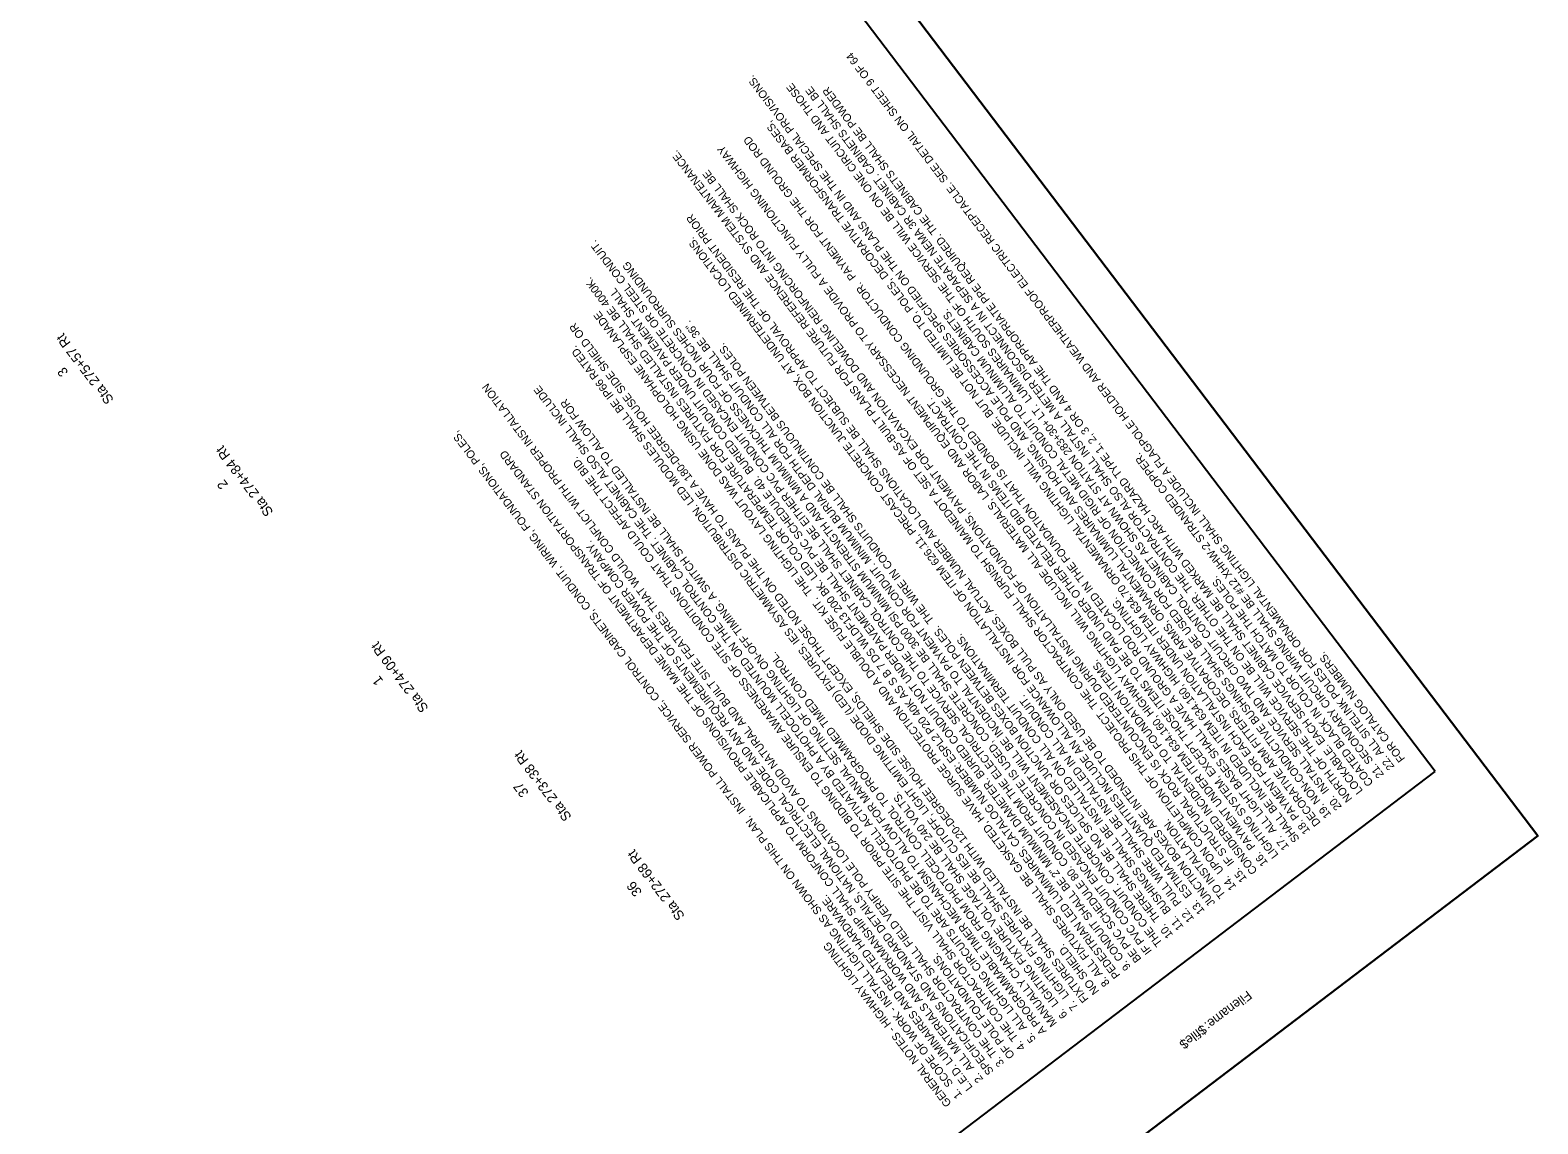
# Model space of a CAD drawing. Extents: x 1111477 to 1112429, y 616480 to 617490.
# Drawn here: x 1111891 to 1112429, y 616710 to 617100 of the extents above; entities that cross this region are included whole.
import ezdxf

# ---------------------------------------------------------------- set-up
doc = ezdxf.new("R2010")
doc.units = 0
for name, color, linetype in [('ANNOTATION', 7, 'Continuous'), ('D_LIGHTING_ANNOTATION', 7, 'Continuous'), ('VSL-LUMINAIRESCHEDULES', 7, 'Continuous'), ('VSL-STATISTICS', 7, 'Continuous')]:
    doc.layers.add(name, color=color, linetype=linetype)

msp = doc.modelspace()

# ---------------------------------------------------------------- linework, layer by layer
msp.add_lwpolyline([(1111990.86, 616480.3), (1111476.68, 617157.15), (1111914.64, 617489.85), (1112428.82, 616813)], close=True)
at = {"layer": 'VSL-LUMINAIRESCHEDULES'}
msp.add_lwpolyline([(1112428.82, 616813), (1111914.64, 617489.85), (1111476.68, 617157.15), (1111990.86, 616480.3)], close=True, dxfattribs=at)
at = {"layer": 'VSL-STATISTICS'}
for p, q in [((1112392.16, 616835.98), (1111908.23, 617473.01)), ((1111974.11, 616518.4), (1112392.16, 616835.98))]:
    msp.add_line(p, q, dxfattribs=at)

# ---------------------------------------------------------------- texts
at = {"layer": 'ANNOTATION'}
for s, p in [('22. ALL SITELINK POLES FOR ORNAMENTAL LIGHTING SHALL INCLUDE A FLAGPOLE HOLDER AND WEATHERPROOF ELECTRIC RECEPTACLE. SEE DETAIL ON SHEET 9 OF 64 ', (1112377.82, 616837.68)), ('DECORATIVE ARM FITTERS, DECORATIVE ARMS, ORNAMENTAL LUMINAIRES AND HOUSING, AND POLE ACCESSORIES SPECIFIED ON THE PLANS AND IN THE SPECIAL PROVISIONS.', (1112351.48, 616817.68)), ('20.  INSTALL SERVICE AND TWO CIRCUIT CONTROL CABINET AS SHOWN AT STATION 283+30+ LT.  LUMINAIRES SOUTH OF THE SERVICE WILL BE ON ONE CIRCUIT AND THOSE', (1112359.01, 616823.39)), ('NORTH OF THE SERVICE WILL BE ON THE OTHER. THE CONTRACTOR ALSO SHALL INSTALL A METER DISCONNECT IN A SEPARATE NEMA 3R CABINET. CABINETS SHALL BE', (1112362.77, 616826.25)), ('LOCKABLE. EACH SERVICE CABINET SHALL BE MARKED WITH ARC HAZARD TYPE 1, 2, 3 OR 4 AND THE APPROPRIATE PPE REQUIRED. THE CABINETS SHALL BE POWDER', (1112366.53, 616829.11)), ('18. PAYMENT FOR EACH INSTALLATION UNDER ITEM 634.70 ORNAMENTAL LIGHTING WILL INCLUDE, BUT NOT BE LIMITED TO, POLES, DECORATIVE TRANSFORMER BASES,', (1112347.72, 616814.82)), ('17.  ALL LIGHT BASES SHALL HAVE A GROUND ROD LOCATED IN THE FOUNDATION THAT IS BONDED TO THE GROUNDING CONDUCTOR.  PAYMENT FOR THE GROUND ROD', (1112340.2, 616809.1)), ('14.  UPON COMPLETION OF THIS PROJECT, THE CONTRACTOR SHALL FURNISH TO MAINEDOT A SET OF AS-BUILT PLANS FOR FUTURE REFERENCE AND SYSTEM MAINTENANCE.', (1112321.38, 616794.81)), ('16.  PAYMENT UNDER ITEM 634.160, HIGHWAY LIGHTING WILL INCLUDE ALL MATERIALS, LABOR AND EQUIPMENT NECESSARY TO PROVIDE A FULLY FUNCTIONING HIGHWAY', (1112332.67, 616803.39)), ('15.  IF STRUCTURAL ROCK IS ENCOUNTERED DURING INSTALLATION OF FOUNDATIONS, PAYMENT FOR EXCAVATION AND DOWELING REINFORCING INTO ROCK SHALL BE', (1112325.15, 616797.67)), ('JUNCTION BOXES ARE INTENDED TO BE USED ONLY AS PULL BOXES. ACTUAL NUMBER AND LOCATIONS SHALL BE SUBJECT TO APPROVAL OF THE RESIDENT PRIOR', (1112313.86, 616789.1)), ('BE PVC SCHEDULE 80. CONDUIT FROM THE ELECTRICAL SERVICE TO THE CONTROL CABINET SHALL BE EITHER PVC CONDUIT ENCASED IN CONCRETE OR STEEL CONDUIT.', (1112287.52, 616769.09)), ('13.  ESTIMATED QUANTITIES INCLUDE AN ALLOWANCE FOR INSTALLATION OF ITEM 626.11, PRECAST CONCRETE JUNCTION BOX, AT UNDETERMINED LOCATIONS.', (1112310.1, 616786.24)), ('IF PVC CONDUIT ENCASED IN CONCRETE IS USED, CONCRETE SHALL BE 3000 PSI MINIMUM STRENGTH AND A MINIMUM THICKNESS OF FOUR INCHES SURROUNDING', (1112291.28, 616771.95)), ('PEDESTRIAN LED LUMINAIRES, CATALOG NUMBER: ESPL2 P20 40K AS S B 7 DS WLDF13 200 BK. LED COLOR TEMPERATURE FOR FIXTURES INSTALLED SHALL BE 4000K.', (1112280, 616763.37)), ('9. CONDUIT SHALL BE 2" MINIMUM DIAMETER. BURIED CONDUIT NOT UNDER PAVEMENT SHALL BE PVC SCHEDULE 40.  BURIED CONDUIT UNDER PAVEMENT SHALL', (1112283.76, 616766.23)), ('8. ALL FIXTURES SHALL BE GASKETED, HAVE SURGE PROTECTION AND A DOUBLE FUSE KIT.  THE LIGHTING LAYOUT WAS DONE USING HOLOPHANE ESPLANADE', (1112276.23, 616760.51)), ('19. NON-CONDUCTIVE BUSHINGS SHALL BE USED FOR CONNECTION OF RIGID METAL CONDUIT TO ALUMINUM CABINETS.', (1112355.25, 616820.54)), ('FIXTURES SHALL BE INSTALLED WITH 120-DEGREE HOUSE SIDE SHIELDS, EXCEPT THOSE NOTED ON THE PLANS TO HAVE A 180-DEGREE HOUSE SIDE SHIELD OR', (1112268.71, 616754.8)), ('THE CONDUIT. CONCRETE ENCASEMENT WILL BE INCIDENTAL TO PAYMENT FOR CONDUIT. MINIMUM BURIAL DEPTH FOR ALL CONDUIT SHALL BE 36". ', (1112295.05, 616774.8)), ('7.  LIGHTING FIXTURES SHALL BE IES CUTOFF, LIGHT EMITTING DIODE (LED) FIXTURES, IES ASYMMETRIC DISTRIBUTION. LED MODULES SHALL BE IP66 RATED.', (1112264.95, 616751.94)), ('10.  THERE SHALL BE NO SPLICES OR JUNCTION BOXES BETWEEN POLES.  THE WIRE IN CONDUITS SHALL BE CONTINUOUS BETWEEN POLES.  ', (1112298.81, 616777.66)), ('3. THE CONTRACTOR SHALL FIELD VERIFY POLE LOCATIONS TO AVOID NATURAL AND BUILT SITE FEATURES THAT WOULD CONFLICT WITH PROPER INSTALLATION', (1112238.61, 616731.93)), ('5.  ALL LIGHTING CIRCUITS ARE TO BE PHOTOCELL ACTIVATED BY A PHOTOCELL MOUNTED ON THE CONTROL CABINET. THE CABINET ALSO SHALL INCLUDE ', (1112249.9, 616740.51)), ('A PROGRAMMABLE TIMER MECHANISM TO ALLOW FOR MANUAL SETTING OF LIGHTING ON-OFF TIMING. A SWITCH SHALL BE INSTALLED TO ALLOW FOR ', (1112253.66, 616743.36)), ('LIGHTING SYSTEM, EXCEPT THOSE ITEMS TO BE PAID UNDER OTHER RELATED BID ITEMS IN THE CONTRACT.', (1112336.43, 616806.24)), ('1.  SCOPE OF WORK - INSTALL LIGHTING AS SHOWN ON THIS PLAN.  INSTALL POWER SERVICE, CONTROL CABINETS, CONDUIT, WIRING, FOUNDATIONS, POLES,', (1112223.56, 616720.5)), ('2.  ALL MATERIALS AND WORKMANSHIP SHALL CONFORM TO APPLICABLE PROVISIONS OF THE MAINE DEPARTMENT OF TRANSPORTATION STANDARD', (1112231.08, 616726.21)), ('21. SECONDARY CIRCUIT WIRING SHALL BE #12 XHHW-2 STRANDED COPPER.', (1112374.06, 616834.83)), ('4. THE CONTRACTOR SHALL VISIT THE SITE PRIOR TO BIDDING TO ENSURE AWARENESS OF SITE CONDITIONS THAT COULD AFFECT THE BID.', (1112246.13, 616737.65)), ('SPECIFICATIONS AND STANDARD DETAILS, NATIONAL ELECTRICAL CODE AND ANY REQUIREMENTS OF THE POWER COMPANY.', (1112234.85, 616729.07)), ('COATED BLACK IN COLOR TO MATCH THE POLES.', (1112370.3, 616831.97)), ('SHALL BE INCLUDED IN ITEM 634.160, HIGHWAY LIGHTING.', (1112343.96, 616811.96)), ('11.  BUSHINGS SHALL BE INSTALLED ON ALL CONDUIT TERMINATIONS.', (1112302.57, 616780.52)), ('MANUALLY CHANGING FROM PHOTOCELL CONTROL TO PROGRAMMED TIMED CONTROL.', (1112257.42, 616746.22)), ('CONSIDERED INCIDENTAL TO FOUNDATION ITEMS.', (1112328.91, 616800.53)), ('FOR CATALOG NUMBERS.', (1112381.58, 616840.54)), ('12.  PULL WIRE SHALL BE INSTALLED IN ALL CONDUIT.', (1112306.33, 616783.38)), ('6.  LIGHTING FIXTURE VOLTAGE SHALL BE 240 VOLTS.', (1112261.18, 616749.08)), ('TO INSTALLATION.', (1112317.62, 616791.95)), ('L.E.D. LUMINAIRES AND RELATED HARDWARE. ', (1112227.32, 616723.36)), ('GENERAL NOTES - HIGHWAY LIGHTING', (1112219.8, 616717.64)), ('NO SHIELD.', (1112272.47, 616757.65)), ('OF POLE FOUNDATIONS.', (1112242.37, 616734.79))]:
    msp.add_text(s, height=2.835, rotation=127.2225, dxfattribs=at).set_placement(p)
at = {"layer": 'D_LIGHTING_ANNOTATION'}
for s, p in [('Sta 275+57 Rt', (1111920.98, 616968.59)), ('3', (1111904.75, 616978.39)), ('Sta 274+84 Rt', (1111977.91, 616928.56)), ('2', (1111961.74, 616938.27)), ('Sta 274+09 Rt', (1112033.26, 616858.63)), ('1', (1112017.12, 616868.3)), ('Sta 273+38 Rt', (1112084.31, 616819.87)), ('37', (1112069.03, 616828.41)), ('Sta 272+68 Rt', (1112124.68, 616784.51)), ('36', (1112109.43, 616793.02))]:
    msp.add_text(s, height=3.5, rotation=127.2225, dxfattribs=at).set_placement(p)
at = {"layer": 'VSL-STATISTICS'}
for s, p in [('Filename:', (1112325.19, 616758.01)), ('$file$', (1112309.16, 616745.83))]:
    msp.add_text(s, height=3.348, rotation=217.2225, dxfattribs=at).set_placement(p)

doc.saveas('drawing.dxf')
